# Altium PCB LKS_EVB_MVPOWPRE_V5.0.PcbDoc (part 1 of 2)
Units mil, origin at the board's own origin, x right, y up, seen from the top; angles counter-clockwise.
Board outline 11300 x 7874.02 mil, 2 copper layers (Top Layer, Bottom Layer); 150 components, 96 nets, 404 pads, 334 vias.
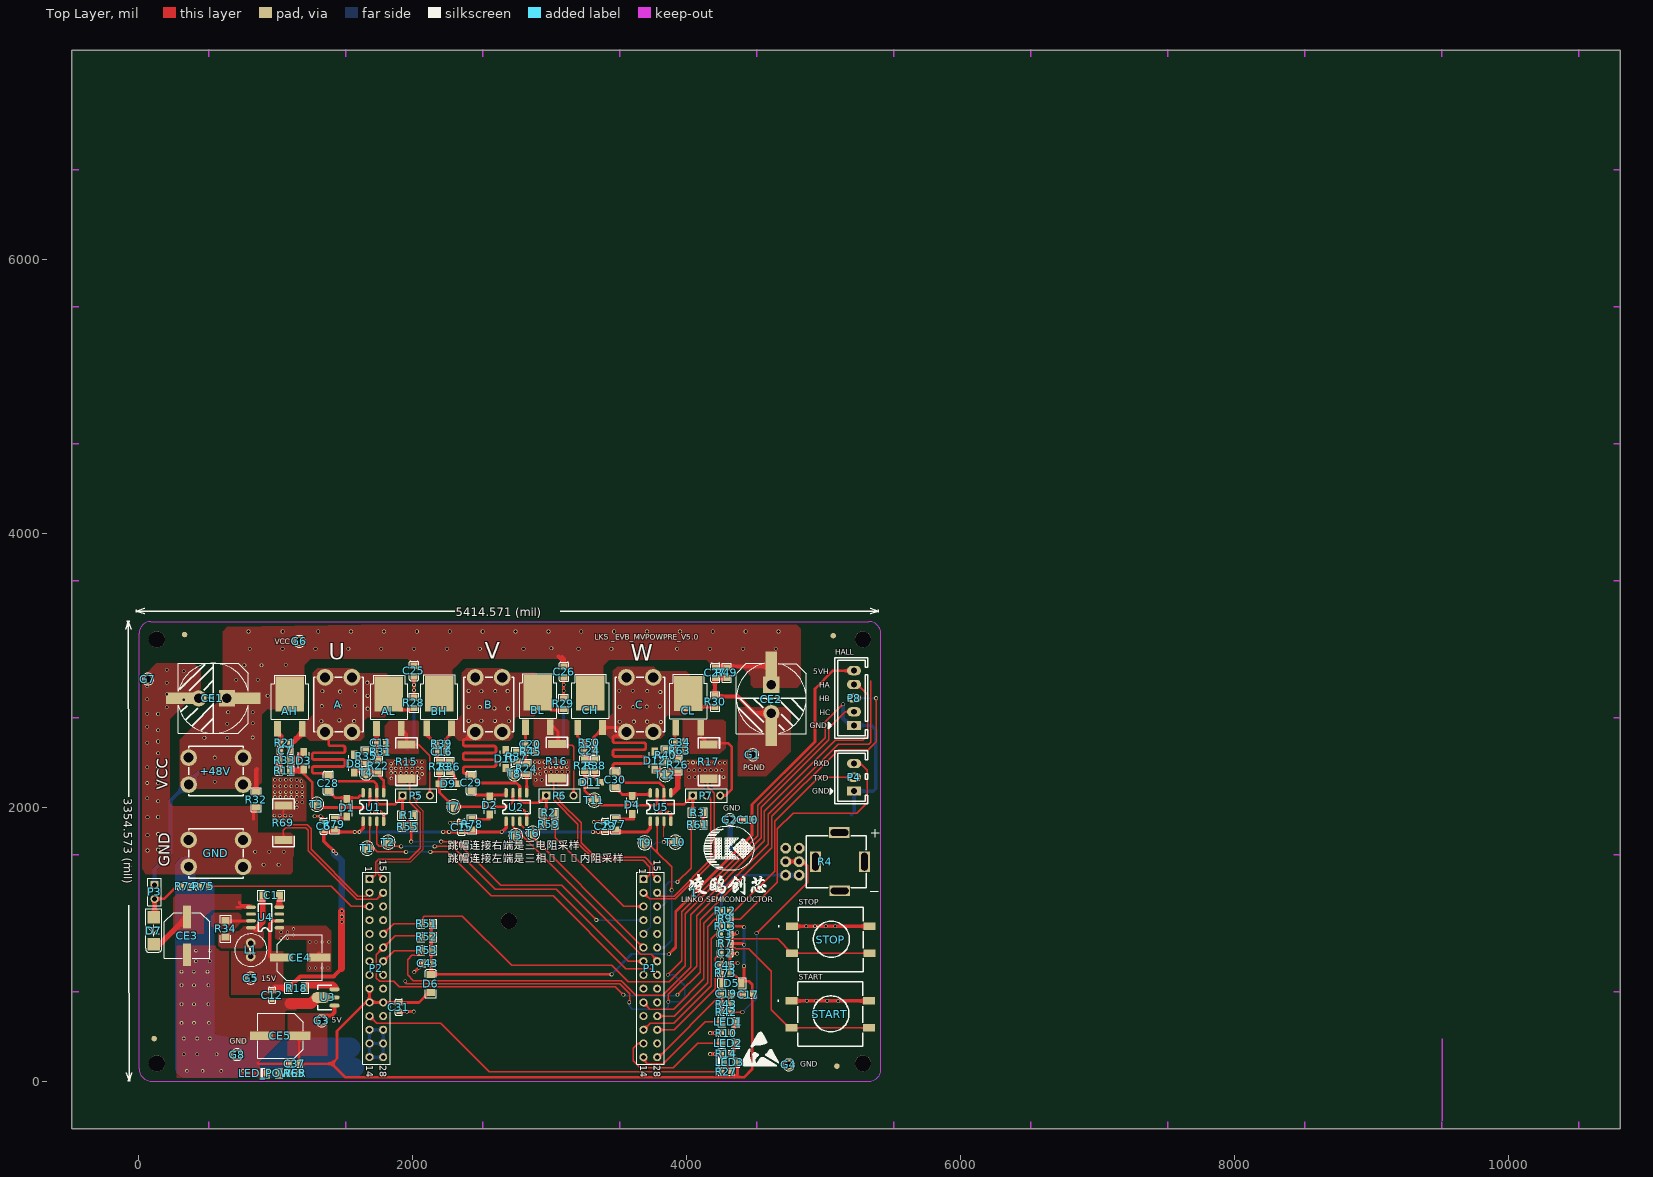
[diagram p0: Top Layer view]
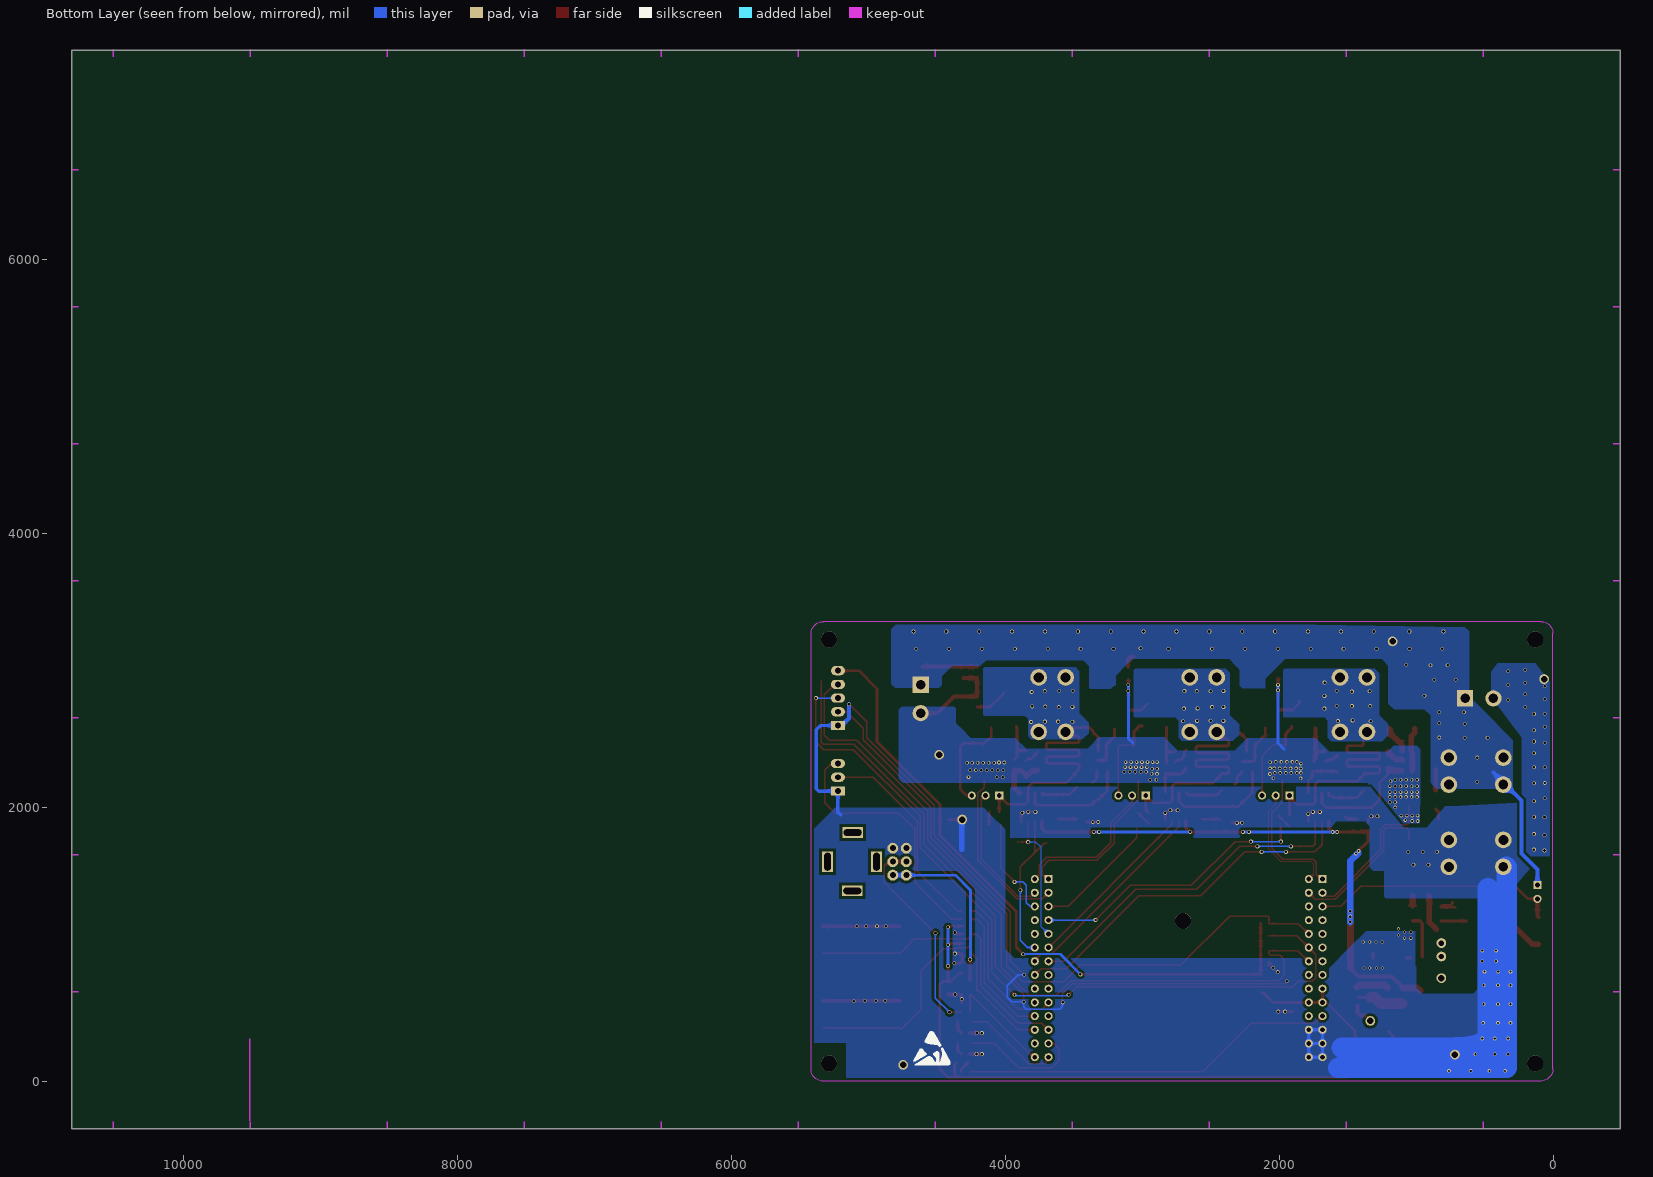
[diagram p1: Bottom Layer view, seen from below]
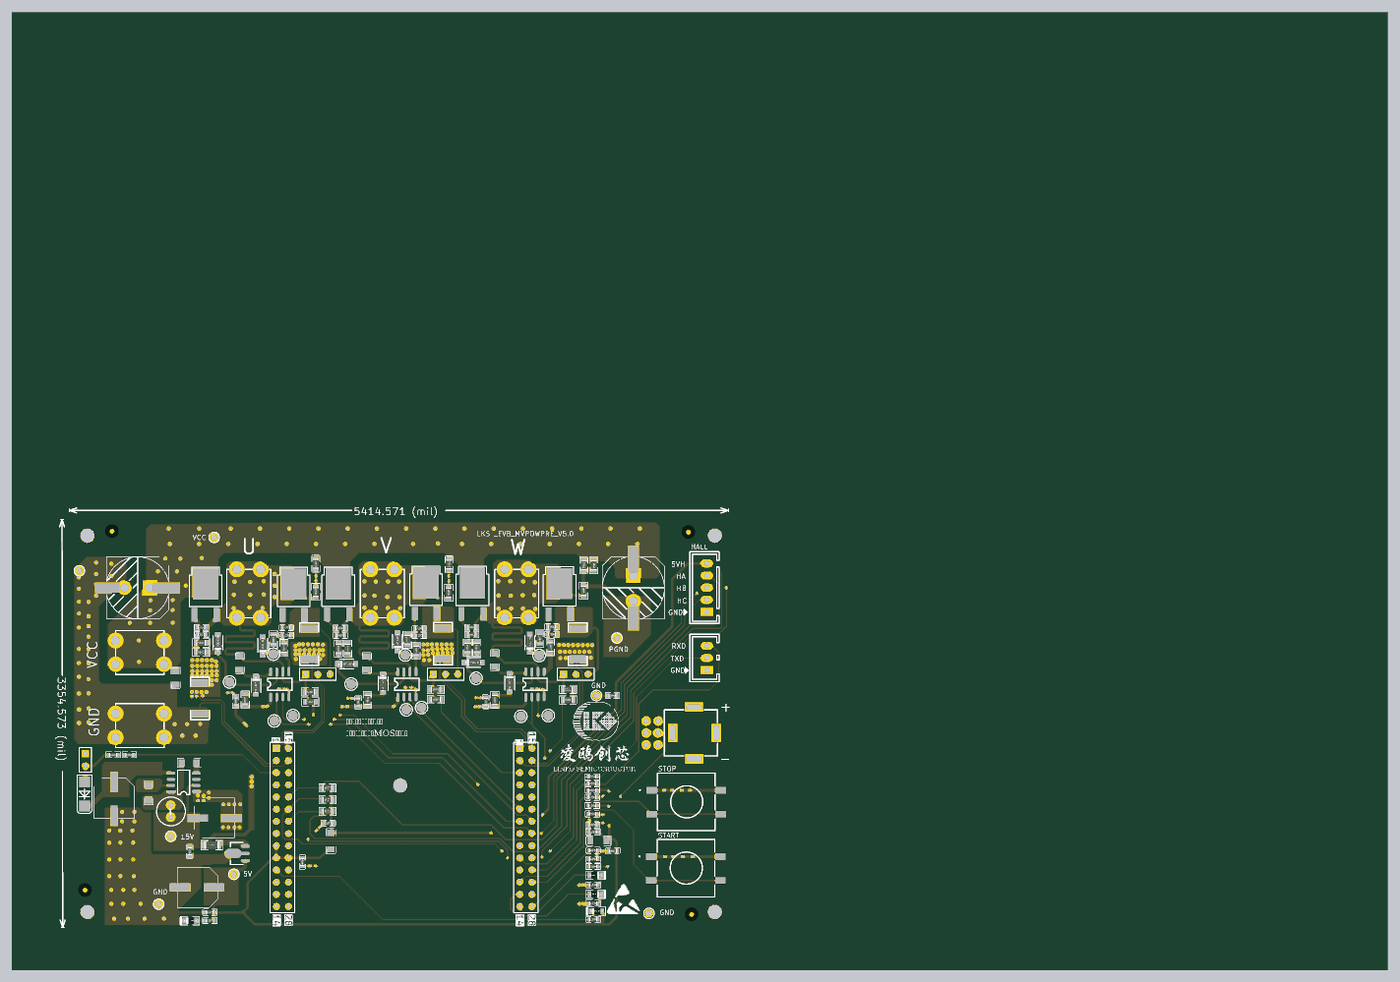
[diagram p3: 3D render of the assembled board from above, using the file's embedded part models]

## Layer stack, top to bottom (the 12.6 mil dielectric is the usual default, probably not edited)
Top Solder: solder mask 0.4, Solder Resist, Dk 3.5
Top Layer: signal copper 1.4
Dielectric1: dielectric 12.6, FR-4, Dk 4.8
Bottom Layer: signal copper 1.4
Bottom Solder: solder mask 0.4, Solder Resist, Dk 3.5

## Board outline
-489.2,7526.27 10810.8,7526.27 10810.8,-347.74 -489.2,-347.74

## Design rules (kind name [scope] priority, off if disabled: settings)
Clearance [InPolygon] p1: gap=20 ignorepadtopadclearanceinfootprint=FALSE except(0: Arc-Hole Track-Hole SMDPad-Hole THPad-Hole Via-Hole Fill-Hole Poly-Hole Region-Hole Text-Hole)
Clearance Clearance_48V [InNet('+48V')] p2: gap=30 ignorepadtopadclearanceinfootprint=FALSE except(0: Arc-Hole Track-Hole SMDPad-Hole THPad-Hole Via-Hole Fill-Hole Poly-Hole Region-Hole Text-Hole)
Clearance Clearance_4 [InNet('PGND')] p3 off: gap=20 ignorepadtopadclearanceinfootprint=FALSE except(0: Arc-Hole Track-Hole SMDPad-Hole THPad-Hole Via-Hole Fill-Hole Poly-Hole Region-Hole Text-Hole)
Clearance Clearance_5V [InNet('+5V')] p4 off: gap=20 ignorepadtopadclearanceinfootprint=FALSE except(0: Arc-Hole Track-Hole SMDPad-Hole THPad-Hole Via-Hole Fill-Hole Poly-Hole Region-Hole Text-Hole)
Clearance Clearance_15V [InNet('+15V')] p5: gap=20 ignorepadtopadclearanceinfootprint=FALSE except(0: Arc-Hole Track-Hole SMDPad-Hole THPad-Hole Via-Hole Fill-Hole Poly-Hole Region-Hole Text-Hole)
Clearance Clearance_5 [All] p6: gap=10 ignorepadtopadclearanceinfootprint=FALSE except(0: Arc-Hole Track-Hole SMDPad-Hole THPad-Hole Via-Hole Fill-Hole Poly-Hole Region-Hole Text-Hole)
ComponentClearance [All] p1 off: gap=0 collisioncheckmode=3 verticalgap=0 showdistances=FALSE
FabricationTestpoint [(IsPad And (OnTopLayer Or OnBottomLayer))] p1: side=3 testpointundercomponent=TRUE minsize=40 maxsize=100 preferedsize=60 minholesize=0 maxholesize=40 preferedholesize=32 testpointgrid=1 allowsidetop=TRUE allowsidebottom=TRUE usegrid=TRUE gridtolerance=0.01
HoleSize [All] p1: absolutevalues=TRUE maxlimit=200 minlimit=1 maxpercent=80.000 minpercent=20.000
PlaneConnect [All] p1: planeconnectstyle=Direct reliefexpansion=20 reliefentries=4 reliefconductorwidth=10 reliefairgap=10
PolygonConnect [All] p1: connectstyle=Direct reliefconductorwidth=30 reliefentries=4 polygonreliefangle="90 Angle" airgapwidth=10
RoutingVias [All] p1: holewidth=13.78 width=19.68 viastyle="Through Hole" minholewidth=0 minwidth=19.68 maxholewidth=19.68 maxwidth=39.37
SilkToSolderMaskClearance SilkscreenOverComponentPads [IsPad] p1: minsilkscreentomaskgap=10 clearancetoexposedcopper=TRUE
SolderMaskExpansion [All] p1: expansion=4 istentingtop=FALSE
Width Width_2 [All] p1 off: maxlimit=10 minlimit=10 preferedwidth=10
Width Width_1 [InNet('5V-T')] p2 off: maxlimit=40 minlimit=40 preferedwidth=40
Width Width_VH [InNet('5V1')] p3 off: maxlimit=40 minlimit=40 preferedwidth=40
Width Width_5V [InNet('5V')] p4 off: maxlimit=40 minlimit=40 preferedwidth=40
Width Width_14.3V [InNet('+14.3V')] p5 off: maxlimit=50 minlimit=50 preferedwidth=50
Width Width_15V [InNet('+15V')] p6 off: maxlimit=40 minlimit=40 preferedwidth=40
Width Width_48V [InNet('+48V')] p7 off: maxlimit=40 minlimit=40 preferedwidth=40
Width [All] p8: maxlimit=200 minlimit=1 preferedwidth=40
25 further rules are at their usual default settings.

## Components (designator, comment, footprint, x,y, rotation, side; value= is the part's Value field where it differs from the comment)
1 "LKS_sign" LKS_LOGO2 4052,1375 r0 top
+48V "M4" M4_CONECTOR 362.32,2361.91 r180 top locked
A "M4" M4_CONECTOR 1554.74,2947.17 r90 top
AH "NCE8259AK" TO-252 1100.83,2699.83 r0 top
AL "NCE8259AK" TO-252 1824.46,2700.27 r0 top
B "M4" M4_CONECTOR 2651.89,2947.17 r90 top
BH "NCE8259AK" TO-252 2190.43,2701.83 r0 top
BL "NCE8259AK" TO-252 2911.5,2709.11 r0 top
C "M4" M4_CONECTOR 3754.7,2947.17 r90 top
C1 "1uF/100V" 1206 1025,1355 r180 top value=10uF/100V
C2 "100nF/50V" 0603C 4279.38,935.8 r180 top
C3 "100nF/50V" 0603C 4279,1072.38 r0 top
C6 "100nF/50V" 0603C 1349.35,1861.85 r270 top
C7 "1nF/50V" 0603C 1067.35,2411.48 r0 top
C10 "100nF/10V" 0603C 4443.63,1909.64 r180 top
C11 "1nF/50V" 0603C 1765.67,2469.57 r0 top
C12 "100nF/50V" 0603C 971.91,628.23 r270 top
C15 "100nF/50V" 0603C 2354.32,1854.61 r270 top
C16 "1nF/50V" 0603C 2208.71,2404.53 r0 top
C17 "100nF/50V" 0603C 4447,632.28 r0 top
C19 "100nF/50V" 0603C 4286.37,636.63 r180 top
C20 "1nF/50V" 0603C 2856.37,2461.01 r0 top
C23 "100nF/50V" 0603C 3403.42,1859.96 r270 top
C24 "1nF/50V" 0603C 3287.96,2410.48 r0 top
C25 "100nF/100V" 0805C 2007.32,2994.16 r90 top
C26 "100nF/100V" 0805C 3102.45,2987.49 r90 top
C27 "100nF/100V" 0805C 4208.04,2981.02 r90 top
C28 "10uF/25V" 1206C 1382.65,2175.41 r90 top
C29 "10uF/25V" 1206C 2426.51,2177.17 r90 top
C30 "10uF/25V" 1206C 3477.64,2201.04 r90 top
C31 "100nF/50V" 0603C 1897.23,540.21 r90 top
C34 "1nF/50V" 0603C 3946.98,2474 r0 top
C37 "100nF/50V" 0603C 1136.55,127.54 r0 top
C43 "100nF/50V" 0603C 2109.05,860.11 r0 top value=104
C45 "100nF/50V" 0603C 4281.39,845.92 r180 top value=104
CE1 "220uF/63V" "220UF/63V 12.5*12.5" 643.54,2794.86 r270 top locked
CE2 "220uF/63V" "220UF/63V 12.5*12.5" 4615.51,2894.77 r0 top
CE3 "10UF/100V" "220UF/25V 8*10" 350.56,1061.42 r0 top
CE4 "220uF/25V" "220UF/25V 8*10" 1176,902 r90 top
CE5 "220uF/16V" "220UF/25V 8*10" 1030.55,331.65 r270 top
CH "NCE8259AK" TO-252 3293.7,2707.27 r0 top
CL "NCE8259AK" TO-252 4009.41,2704.65 r0 top
D1 "1N4007/SOD-123" SOD123 1515.74,1995.74 r90 top
D2 "1N4007/SOD-123" SOD123 2558.97,2012.54 r90 top
D3 "1N4007/SOD-123" SOD123 1201.59,2339 r270 top
D4 "1N4007/SOD-123" SOD123 3600.74,2015.98 r90 top
D5 "1N4007" D1206 4263.77,717.72 r0 top
D6 "1N4007" D1206 2131.36,777.78 r270 top
D7 "ES1J" DO-214AC 107.24,1099.38 r270 top
D8 "1N4007/SOD-123" SOD123 1571.43,2317.87 r270 top
D9 "1N4007/SOD-123" SOD123 2258.32,2169.59 r180 top
D10 "1N4007/SOD-123" SOD123 2677.05,2351.93 r270 top
D11 "1N4007/SOD-123" SOD123 3299,2182 r180 top
D12 "1N4007/SOD-123" SOD123 3764.75,2340 r270 top
G1 "PAD1.2" PAD1.2 4480.77,2382.24 r0 top
G2 "PAD1.2" PAD1.2 4312.32,1909.64 r0 top
G3 "PAD1.2" PAD1.2 1333.91,439.87 r0 top
G4 "PAD1.2" PAD1.2 4743.57,118.6 r0 top
G5 "PAD1.2" PAD1.2 815,752.2 r0 top
G6 "PAD1.2" PAD1.2 1171.19,3209.96 r0 top
G7 "PAD1.2" PAD1.2 64.78,2935.27 r0 top
G8 "PAD1.2" PAD1.2 715.92,194.2 r0 top
GND "M4" M4_CONECTOR 362.32,1761.11 r180 top locked
L1 "1mH  6*8" L_DIP_6*8MM 814.94,909.79 r90 top locked
LED1 "LED" SOD323 4300,434 r0 top
LED2 "LED" SOD323 4300,277.89 r0 top
LED3 "LED" SOD323 4314.88,134.7 r180 top
LED_POWER "LED_R" SOD323 978.76,56.48 r180 top
P1 "Header 14X2A" HDR2X14_CEN 3682.62,1475.19 r270 top locked
P2 "Header 14X2A" HDR2X14_CEN 1682.62,1475.19 r270 top locked
P3 "Header 2" HDR1X2 113.86,1430.98 r270 top
P4 "2.54-XH-3A-180" 2.54-XH-3A-180 5219.88,2118.44 r270 top
P5 "Header 3" HDR1X3 1924.05,2084.61 r0 top locked
P6 "Header 3" HDR1X3 2972.79,2084.61 r0 top locked
P7 "Header 3" HDR1X3 4042.39,2084.61 r0 top locked
P8 "Header 5" 2.54-XH-5A-180 5219.52,2796.37 r270 top
R1 "20K 1%" 0805R 1960.48,1940.22 r180 top
R2 "20K 1%" 0805R 2991.11,1958.2 r180 top
R3 "20K 1%" 0805R 4078.34,1960.07 r180 top
R4 "RPot" RK097-W-1 5014.05,1602.13 r270 top value=20K
R7 "10K" 0603R 4279,1005 r180 top
R9 "10R" 0603R 4279,1186.97 r0 top
R10 "5.1K" 0603R 4286.95,351.53 r180 top value=10K
R11 "51R" 0805R 1064,2266 r180 top value=K
R12 "10R" 0603R 4279.38,1242.38 r180 top value=100R
R13 "10K" 0603R 4279,1131.07 r0 top
R14 "5.1K" 0603R 4287,201.8 r180 top value=10K
R15 "0.005R/2512" 2512 1953.12,2455.91 r270 top
R16 "0.005R/2512" 2512 3050.13,2212.58 r90 top
R17 "0.005R/2512" 2512 4159.78,2455.91 r270 top
R18 "10R" 1206R 1151.55,679.32 r0 top value=K
R21 "20K1%" 0603R 1067.35,2469.91 r180 top value=K
R22 "51R" 0805R 1745.67,2301 r270 top value=K
R23 "51R" 0805R 2193.71,2295.93 r90 top value=K
R24 "51R" 0805R 2829.94,2280 r270 top value=K
R25 "51R" 0805R 3253,2304 r90 top value=K
R26 "51R" 0805R 3933,2308 r270 top value=K
R27 "5.1K" 0603R 4287,69 r180 top value=10K
R28 "51K" 0805R 2006.57,2761.64 r270 top value=K
R29 "51K" 0805R 3098.37,2754.95 r270 top value=K
R30 "51K" 0805R 4205.94,2771.18 r270 top value=K
R31 "20K1%" 0603R 1765.67,2405.05 r180 top value=K
R32 "47K" 1206R 856,2054.36 r270 top value=K
R33 "10R" 0805R 1064,2342.59 r180 top value=K
R34 "0.3R" 1206 633,1170 r270 top
R35 "10R" 0805R 1657.59,2370.5 r90 top value=K
R36 "10R" 0805R 2267.71,2295.93 r90 top value=K
R37 "10R" 0805R 2756.51,2368.93 r90 top value=K
R38 "10R" 0805R 3330,2304 r90 top value=K
R39 "20K1%" 0603R 2208.71,2463.73 r180 top value=K
R40 "10R" 0805R 3846.53,2378 r90 top value=K
R42 "10K" 0603R 4286.37,503.95 r180 top value=K
R43 "20K" 0603R 4286.12,563.36 r180 top value=K
R45 "20K1%" 0603R 2858,2403 r180 top value=K
R49 "51K" 0805R 4290.41,2981.02 r270 top value=K
R50 "20K1%" 0603R 3287.96,2471.3 r180 top value=K
R51 "2K" 0805R 2102.27,1149.28 r0 top
R52 "2K" 0805R 2102.27,1052.57 r0 top
R53 "2K" 0805R 2102.27,956.59 r0 top
R55 "20K 1%" 0805R 1961.36,1857.51 r180 top
R59 "20K 1%" 0805R 2992.19,1876.88 r180 top
R61 "20K 1%" 0805R 4079.41,1872.2 r0 top
R63 "20K1%" 0603R 3947,2413 r180 top value=K
R65 "5.1K" 0603R 1136.62,58.99 r180 top value=510R
R69 "0.005R/2512" 2512 1055.03,2009.54 r270 top
R73 "10K" 0603R 4283.13,788.55 r180 top
R74 "20K1%" 0603R 342.59,1422.22 r0 top
R75 "20K1%" 0603R 474.58,1422.18 r0 top
R77 "10R" 0805R 3477.54,1874.89 r90 top
R78 "10R" 0805R 2431.84,1874.57 r90 top
R79 "10R" 0805R 1427,1876.85 r90 top
START "SW-PB" "SW-PB  12*12" 5046.18,487.56 r0 top
STOP "SW-PB" "SW-PB  12*12" 5049.86,1032.41 r0 top
T1 "TestP" TP-80 1665.49,1700.56 r0 top
T2 "TestP" TP-80 1819.68,1744.81 r0 top
T3 "TestP" TP-80 1298.17,2021.23 r0 top
T4 "TestP" TP-80 1657.98,2249.61 r0 top
T5 "TestP" TP-80 2750,1792.49 r0 top
T6 "TestP" TP-80 2875.07,1810.16 r0 top
T7 "TestP" TP-80 2296.9,2003.78 r0 top
T8 "TestP" TP-80 2741.32,2242.5 r0 top
T9 "TestP" TP-80 3691.47,1738.81 r0 top
T10 "TestP" TP-80 3915.86,1745.2 r90 top
T11 "TestP" TP-80 3323.08,2051.79 r0 top
T12 "TestP" TP-80 3841.46,2238 r90 top
U1 "LKS560" SO-8 1638.08,1898.57 r90 top
U2 "LKS560" SO-8 2681.91,1898.57 r90 top
U3 "LM7805" SOT-89 1378.21,611 r90 top
U4 "LKS620" so-8 1024,1122 r180 top
U5 "LKS560" SO-8 3734.03,1898.57 r90 top

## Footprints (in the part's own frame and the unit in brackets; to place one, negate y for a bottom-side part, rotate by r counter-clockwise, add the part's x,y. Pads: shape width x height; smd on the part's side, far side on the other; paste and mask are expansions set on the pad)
2.54-XH-3A-180 [mm]
  rect 1.7x2.6 hole 1.1: 1(0,0)
  oval 1.7x2.6 hole 1.1: 2(-2.54,0) 3(-5.08,0)
  silkscreen extent -7.49,-4.5 2.41,2.54
2.54-XH-5A-180 [mm]
  rect 1.7x2.6 hole 1.1: 1(5.08,0)
  oval 1.7x2.6 hole 1.1: 2(2.54,0) 3(0,0) 4(-2.54,0) 5(-5.08,0)
  silkscreen extent -7.49,-4.78 7.49,2.54
"220UF/25V 8*10" [mm]
  rect 1.5x4.2 smd: 1(0,3.492) 2(0,-3.492)
  silkscreen extent -4.2,-4.13 4.2,4.27
"220UF/63V 12.5*12.5" [mm]
  rect 2.1x5.5 smd: 1(0,3.429)
  rect 3x3 hole 1.778: 1(0,-0.04)
  round 3 hole 1.778: 2(0,-5.3)
  rect 2.1x5 smd: 2(0,-8.867)
  silkscreen extent -6.5,-9.07 6.5,3.93
0603C [mm]
  rect 0.9x0.95 smd: 1(-0.813,0) 2(0.813,0)
  silkscreen extent -1.5,-0.66 1.5,0.66, body extent -0.8,-0.4 0.8,0.4, height 0.45
0603R [mil]
  rect 38x32 smd: 1(-32,0) 2(32,0)
  silkscreen extent -59,-24 59,24, body extent -31,-16 32,16, height 18
0805C [mil]
  rect 46x51.18 smd: 1(-38,0) 2(38,0)
  silkscreen extent -70,-33 70,33, body extent -40,-25 38,25, height 22
0805R [mil]
  rect 46x51.18 smd: 1(-38,0) 2(38,0)
  silkscreen extent -70,-34 70,34, body extent -39,-25 39,25, height 22
1206 [mm]
  rect 1.35x1.45 smd: 1(-0.01,-0.01) 2(2.99,-0.01)
  silkscreen extent -1.02,-1 4,0.98
1206C [mil]
  rect 50x60 smd: 1(-55,0) 2(55,0)
  silkscreen extent -86,-37 86,37
1206R [mil]
  rect 50x60 smd: 1(-55,0) 2(55,0)
  silkscreen extent -88,-39 88,39, body extent -62,-31 64,32, height 24
2512 [mm]
  rect 1.5x3.3 smd: 1(-0.04,-0.01) 2(6.31,-0.01)
  silkscreen extent -1.31,-1.98 7.56,1.96
D1206 [mm]
  rect 1.3x1.6 smd: 1(3.346,-0.04) 2(-0.054,-0.04)
  silkscreen extent -0.97,-1.06 4.26,0.98
DO-214AC [mm]
  rect 2.3x2.3 smd: 1(-2.502,0) 2(2.502,0)
  silkscreen extent -4,-1.51 4,1.52
HDR1X2 [mm] "Connector; Header; 2 Position"
  rect 1.5x1.5 hole 0.9: 1(0,0)
  round 1.5 hole 0.9: 2(2.54,0)
  silkscreen extent -1.27,-1.27 3.81,1.27
HDR1X3 [mm]
  rect 1.5x1.5 hole 0.9: 1(0,0)
  round 1.5 hole 0.9: 2(2.54,0) 3(5.08,0)
  silkscreen extent -1.27,-1.27 6.35,1.27
HDR2X14_CEN [mm] "Connector; Header; 14x2 Position"
  rect 1.5x1.5 hole 0.9: 1(0,0)
  round 1.5 hole 0.9: 2(2.54,0) 3(5.08,0) 4(7.62,0) 5(10.16,0) 6(12.7,0) 7(15.24,0) 8(17.78,0) 9(20.32,0) 10(22.86,0) 11(25.4,0) 12(27.94,0) 13(30.48,0) 14(33.02,0) 15(0,2.54) 16(2.54,2.54) 17(5.08,2.54) 18(7.62,2.54) 19(10.16,2.54) 20(12.7,2.54) 21(15.24,2.54) 22(17.78,2.54) 23(20.32,2.54) 24(22.86,2.54) 25(25.4,2.54) 26(27.94,2.54) 27(30.48,2.54) 28(33.02,2.54)
  silkscreen extent -1.27,-1.27 34.29,3.81
L_DIP_6*8MM [mm]
  round 1.8 hole 1: 1(0,0) 2(2.5,0)
  silkscreen extent -1.8,-3.04 4.2,2.95
LKS_LOGO2 [mil] "标?"
  silkscreen extent 70,167 440,482
M4_CONECTOR [mm] "接?"
  round 3.1 hole 1.9: 1(-10.1,0) 1(-10.1,5) 1(0,0)
  round 3.1 hole 1.8: 1(0,5)
  silkscreen extent -10.1,-2.1 0,7.1
PAD1.2 [mm]
  round 1.8 hole 1.2: 1(0,0)
  silkscreen extent -1.1,-1.1 1.1,1.1
RK097-W-1 [mm] "电?"
  rect 2x3.8 hole 1.2 slot 3.3 at 90 deg: 0(-5.4,2.503) 0(5.4,2.554)
  rect 3.8x2 hole 1.2 slot 3.3 at 0 deg: 0(0,7.15) 0(0,-1.93)
  round 2.032 hole 1.1: 1(2.5,-7.45) 2(-2.5,-7.45) 3(0,-7.45) 4(-2.5,-4.95) 5(0,-4.95) 6(2.5,-4.95)
  silkscreen extent -4.8,-3.65 4.8,7.45
SO-8 [mm]
  oval 1.8x0.61 smd: 1(-0.02,0.05) 2(-0.02,-1.22) 3(-0.02,-2.49) 4(-0.02,-3.76) 5(5.238,-3.76) 6(5.238,-2.49) 7(5.238,-1.22) 8(5.238,0.05)
  silkscreen extent 1.35,-4.4 3.89,0.68
so-8 [mm]
  oval 1.8x0.61 smd: 1(-0.02,0.05) 2(-0.02,-1.22) 3(-0.02,-2.49) 4(-0.02,-3.76) 5(5.238,-3.76) 6(5.238,-2.49) 7(5.238,-1.22) 8(5.238,0.05)
  silkscreen extent 1.35,-4.4 3.89,0.68
SOD123 [mm] "SOD-123; 2 Leads; Body 2.7 x 1.6 mm, (LxW)"
  rect 1.5x1.22 smd: 1(-1.65,0) 2(1.65,0)
  silkscreen extent -1.55,-1.03 1.38,1.02, body extent -1.93,-0.82 1.93,0.87, height 0.92
SOD323 [mil]
  rect 43.31x50 smd: 1(-40,-2) 2(45.63,-2)
  silkscreen extent -72,-37 87,33, body extent -48,-28 54,24, height 39
SOT-89 [mm]
  oval 0.7x1.9 smd: 1(-1.5,-1.25) 3(1.5,-1.25)
  oval 2x3.5 smd: 2(0,1.25)
  oval 0.7x2.1 smd: 2(0,-1.15)
  silkscreen extent -2.3,-0.75 2.3,1.85
"SW-PB  12*12" [mm] "按?"
  rect 2.2x1.397 smd: 1(-7.2,2.5) 2(-7.2,-2.5) 3(7.2,2.5) 4(7.2,-2.5)
  silkscreen extent -9.75,-5.94 6.02,6.06
TO-252 [mm]
  rect 1.25x2.85 smd: 1(-2.3,-3.2) 3(2.3,-3.2)
  rect 5.3x6.5 smd: 2(0,3.2)
  silkscreen extent -3.4,-1.5 3.4,6.71
TP-80 [mil]
  round 80 smd: 1(-0.39,0.39)
  silkscreen extent -51,-51 51,51

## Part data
+48V A B C GND: library part Socket, "Socket"
AH AL BH BL CH CL: library part MOS
C1 C43 C45: library part Cap, "Capacitor"
C2 C3 C7 C10 C11 C12 C16 C20 C24 C25 C26 C27 C34: library part CAP, "Capacitor"
C6 C15 C17 C19 C23 C31 C37: library part C, "Capacitor"
C28 C29 C30: library part Capacitor, "Capacitor --贴片电容"
CE1 CE2 CE3 CE4 CE5: library part "Capacitor Pol", "Capacitor---电解电容"
D1 D2 D3 D4 D7 D8 D9 D10 D11 D12: library part Diode, "Default Diode", PackageDocument=Sep-1996
D5 D6: library part "Diode 1N4007", "1 Amp General Purpose Rectifier"
G1 G2 G3 G4 G5 G6 G7 G8: library part CON1, "Connector"
L1: library part L
LED_POWER: library part LED
P1 P2: "Header, 14-Pin, Dual row"
P3: "Header, 2-Pin"
P4: library part "Header 3", "Header, 3-Pin"
P5 P6 P7: "Header, 3-Pin"
P8: "Header, 5-Pin"
R1 R2 R3 R51 R52 R53 R55 R59 R61: library part RES/1
R4: "Potentiometer"
R7 R9 R10 R12 R13 R14 R27 R34 R65 R73: library part Res2, "Resistor"
R11 R18 R21 R22 R23 R24 R25 R26 R31 R32 R33 R39 R42 R43 R45 R50 R63: library part Res, "Resistor"
R15 R16 R17 R69 R77 R78 R79: library part RES2短
R28 R29 R30 R35 R36 R37 R38 R40 R49: library part 1Res, "Resistor"
R74 R75: library part R
START STOP: "Switch"
U1 U2 U5: library part IRS2003S
U3: library part VOL-78

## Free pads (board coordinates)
  round 39.37 / inner round 0 / far side round 0 all layers, no hole: 1(111.08,310.73) 3(332.8,3260) 3(5067.77,3252.1) 4(5094.33,109.23)
  round 118.11 hole 118.11: 3(130,130) 3(130,3224.57) 3(2700,1170) 3(5284.57,130) 3(5284.57,3224.57)

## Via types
v1: diameter 26, hole 16, Top Layer to Bottom Layer, 130 vias
v2: diameter 28, hole 18, Top Layer to Bottom Layer, 77 vias
v3: diameter 26, hole 18, Top Layer to Bottom Layer, 55 vias
v4: diameter 28, hole 20, Top Layer to Bottom Layer, 54 vias
v5: diameter 23.62, hole 15.75, Top Layer to Bottom Layer, 14 vias
v6: diameter 27.99, hole 20, Top Layer to Bottom Layer, 4 vias

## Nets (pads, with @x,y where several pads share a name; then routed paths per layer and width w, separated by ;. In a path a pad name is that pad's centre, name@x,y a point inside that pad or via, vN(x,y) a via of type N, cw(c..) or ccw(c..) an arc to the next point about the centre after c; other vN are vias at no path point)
5V-T: C45.2 D5.2 R4.1 R4.6 R73.2 | length 1259.6
  Top Layer w20: 4255.12,805.62 4255.12,862.09 v4(4255.13,888.46) ; D5.2@4255.58,732.07 4255.58,805.16
  Bottom Layer w20: 4252.08,902.66 4252.08,1393.58 4362.21,1503.71 R4.6@4819.17,1503.71
5VH: C10.1 C43.2 D6.2 P8.5 R51.2 R52.2 R53.2 | length 4885
  Top Layer w20: D6.2@2129.79,779.9 v2@3449.45,779.9 ; R52.2@2132.91,1062.49 R52.2@2133.12,1062.49 ; D6.2@2133.12,783.23 R51.2@2133.12,1150.16 ; v2(3867.8,927.09) 3918.11,977.4 3918.11,1237.69 4475.51,1795.09 4475.51,2019.09 4934.05,2477.63 4934.05,2863.94 5066.48,2996.37 P8.5@5219.52,2996.37
  Bottom Layer w15: 3596.72,927.09 v2(3867.8,927.09)
  Bottom Layer w20: v2(3449.45,779.82) 3596.72,927.09
+5V: C17.2 C31.2 C37.2 CE5.1 D5.1 D6.1 G3.1 LED3.1 P2.9 P2.10 P2.24 R7.1 R13.2 R65.1 R73.1 U3.1 | length 6539.5
  Top Layer w20: C37.2@1168.55,127.54 C37.2@1168.55,127.54 ; R65.1@1168.62,58.99 C37.2@1168.55,127.54 ; 1199.3,362.9 CE5.1@1168.05,331.65 1168.62,331.08 C37.2@1168.55,127.54 ; P2.9@1682.62,675.19 P2.10@1682.62,575.19 ; D6.1@2129.79,646.05 2114.3,646.05 2043.45,575.19 P2.24@1782.62,575.19 P2.10@1682.62,575.19 ; R13.2@4308.38,1131.07 4407.81,1131.07 v3(4416.42,1122.46) ; R7.1@4311,1005 4406.49,1005 v3@4415.95,995.54 ; R73.1@4312.48,788.56 4332.94,788.56 D5.1@4405.44,716.06 ; LED3.1@4354.88,136.7 4369,122.58 4369,51.16 4345.84,28 ; D5.1@4402.56,729.63 4453.82,729.63 4476.45,707 4476.45,88.56 4415.89,28 4345.84,28 ; D5.1@4405.54,716.1 4415.89,726.44 v4(4415.89,841.54) ; C37.2@1168.55,127.54 1406.79,127.54 ; 1406.79,127.54 1445.55,166.3 1445.55,366.07 1654.67,575.19 P2.10@1682.62,575.19 ; 1406.79,127.54 1506.33,28 4345.84,28
  Top Layer w30: 1373.44,479.4 1406.79,479.4 1427.43,500.03 U3.1@1427.43,551.94
  Bottom Layer w20: v4@4415.95,841.61 v3@4415.95,995.54 ; v3(4416.41,996.39) v3(4416.42,1122.46)
+15V: C6.2 C12.1 C15.2 C23.2 CE4.1 G5.1 L1.1 R18.1 R77.1 R78.1 R79.1 U1.1 U2.1 U4.2 U5.1 | length 5239.7
  Top Layer w24: 954,909 954,1151 973.03,1170.03 U4.2@1024.79,1170.03 ; CE4.1@1038.5,902 CE4.1@1073.8,902 ; C6.2@1349.35,1829.85 1349.35,1751.73 v1@1438.52,1662.57 ; 1478.54,822.23 1480.06,823.76 v2(1480.06,1163.16) v2(1480.06,1201.16) v4(1480.06,1240.63)
  Top Layer w25: C6.2@1349.35,1819.04 v1(1574.74,1819.04) v1(1608.62,1819.04) 1636.11,1846.53 U1.1@1636.11,1897.79 ; v2(2220.32,1819.04) v2(2648.16,1819.04) 2679.94,1850.81 U2.1@2679.94,1901 ; v2@3314.81,1819.04 3704.88,1819.04 3732.06,1846.21 U5.1@3732.06,1894.22
  Top Layer w30: R18.1@1096.56,679.32 1096.56,684.32 1177.24,765 1421.31,765 1478.54,822.23
  Top Layer w50: C12.1@971.91,660.23 991,679.32 R18.1@1096.56,679.32 ; 1478.54,822.23 v4@1478.54,1241.5
  Bottom Layer w24: v2@1480.06,1162.5 v2(1480.06,1163.16)
  Bottom Layer w25: v1@1580,1819.04 v2(2263.12,1819.04) ; v2(2648.16,1819.04) v2@3352.21,1819.04
  Bottom Layer w50: 1421.57,1666.77 1480.06,1608.28 v4(1480.06,1240.63) v2(1480.06,1201.16) v2(1480.06,1163.16)
  other v1: 1438.66,1661.06 1418.83,1680.21
  other v2: 3313.38,1819.04 3352.14,1819.04
+48V: +48V.1 AH.2 BH.2 C25.2 C26.2 C27.2 CE1.1 CE2.1 CH.2 G6.1 P3.1 R32.1 R49.1 | length 1643.9
  Top Layer w30: R32.1@856,2121.86 856,2273.43 859.25,2276.68 ; 3061.95,3100.35 3102,3060.3 3102.45,3060.3 ; 3088.36,3095.81 3102.45,3081.71 3102.45,3060.3 ; C26.2@3102.45,3025.49 3102.45,3060.3 ; C27.2@4203.92,3028.04 CE2.1@4602.93,3028.04
  Bottom Layer w30: P3.1@113.86,1430.98 113.86,1544.69 230.14,1660.97 230.14,2047.73 435.6,2253.2
  other v3: 554.58,2187.07 553.03,2362.5 478.11,2507.09 645.5,2507.09 832,2508.69 645.5,2609.64 829.77,2612.24 650,2692.37 831.35,2694.28 938.25,2813.07 710,2930.83 865.63,2930.83 894.3,3035.2 770,3036.41 1070.11,3039.95
  other v4: 808.16,3156.11 1048.16,3156.11 1288.16,3156.11 1528.16,3156.11 1768.16,3156.11 2008.16,3156.11 2248.16,3156.11 2488.16,3156.11 2806.33,3156.11 3208.16,3156.11 3448.16,3156.11 3688.16,3156.11 3928.16,3156.11 4168.16,3156.11 4408.16,3156.11 4648.16,3156.11 3010,3160 799.19,3282.46 1048.6,3282.46 1308.42,3282.46 1548.42,3282.46 1788.42,3282.46 2028.42,3282.46 2268.42,3282.46 2508.42,3282.46 2748.42,3282.46 2988.42,3282.46 3228.42,3282.46 3468.42,3282.46 3708.42,3282.46 3948.42,3282.46 4188.42,3282.46 4428.42,3282.46 4668.42,3282.46
DM_IN: D7.1 P3.2 R74.1 | length 370.4
  Top Layer w20: P3.2@113.86,1330.98 183.12,1330.98 274.35,1422.22 R74.1@310.59,1422.22
  Top Layer w30: D7.1@107.24,1197.88 113.86,1204.5 P3.2@113.86,1330.98
GND: C2.1 C3.2 C6.1 C10.2 C12.2 C15.1 C17.1 C19.1 C23.1 C31.1 C37.1 C43.1 C45.1 CE1.2 CE3.2 CE4.2 CE5.2 G2.1 G4.1 G7.1 G8.1 GND.1 LED_POWER.2 P2.12 P2.13 P2.14 P2.16 P2.26 P2.27 P2.28 P4.1 P8.1 R4.2 R4.4 R10.2 R14.2 R32.2 R43.1 R69.2 START.1 START.3 STOP.1 STOP.3 U1.4 U2.4 U3.2 U4.1 U5.4 | length 19842.3
  Top Layer w10: R69.2@1054.64,1761.11 1054.64,1832.63 1072.52,1850.51 1217.31,1850.51 1235.76,1832.05 1235.76,1682.09 1589.52,1328.33 1735.76,1328.33 P2.16@1782.62,1375.19 ; v3(1942.74,729.66) 1942.74,718.48 1949.5,711.73 3509.69,711.73 3582.66,638.75 v3@3582.66,572.57 ; v3(3859.2,776.31) 3961.69,878.81 3961.69,1237.48 4516.95,1792.74 4516.95,2012.54 5010,2505.59 5010,2622.82 v4@5138.84,2751.66 ; v3(3864.62,580.26) 3864.62,632.74 4070,838.12 4070,1207 4593,1730 4593,1948 5106,2461 5327.99,2461 5340,2473.01 5340,2922.93
  Top Layer w20: 831.35,60 832.87,58.48 LED_POWER.2@933.13,58.48 ; 836.24,1911.43 836.24,1967.1 R32.2@856,1986.86 ; 868.05,131.93 872.44,127.54 C37.1@1104.55,127.54 ; v2(1282.09,1933.47) v2(1325.44,1933.47) 1348.2,1910.71 C6.1@1348.2,1887.66 ; U3.2@1329,611 U3.2@1423.49,611 ; v2(1702.01,1965.69) 1770.94,1965.69 v2(1786.11,1950.51) U1.4@1786.11,1897.79 ; C31.1@1897.23,508.21 v2(2006.22,508.21) ; v2(2269.68,1886.33) C15.1@2344.24,1886.33 ; v2(2740.57,1977.18) 2811.3,1977.18 v2(2829.94,1958.55) U2.4@2829.94,1901 ; v1(3319.66,1891.97) C23.1@3403.42,1891.96 ; v2(3778.72,1965.78) 3864.28,1965.78 3882.06,1948 U5.4@3882.06,1894.22 ; C3.2@4310.5,1072.38 4353.38,1072.38 v4(4367,1086) ; G2.1@4312.32,1909.64 4313.28,1908.68 C10.2@4410.13,1908.68 ; C45.1@4313.46,862.8 4313.46,931.1 v2(4365.78,931.1) ; C45.1@4314.18,862.09 v3(4369.37,862.09) ; R43.1@4315.92,570.97 v2(4315.92,599.71) C19.1@4315.92,634.86 ; C19.1@4316.99,632.28 v4(4363,632.28)
  Top Layer w25: v3@2008.61,795.29 C43.1@2074.06,860.75 ; START.1@4762.71,585.99 4899.12,585.99 START.3@5329.63,585.98 ; STOP.1@4766.4,1130.83 STOP.3@5333.33,1130.83
  Top Layer w30: CE4.2@1313.5,902 CE4.2@1313.5,931.5 ; v6(4169,197.25) R14.2@4254.95,197.25 ; v6(4169,350.7) 4169.83,351.53 R10.2@4254.95,351.53 ; v4(4363,632.28) C17.1@4415,632.28
  Top Layer w80: 1100.87,566.16 1255.89,566.16 1300.73,611 U3.2@1329,611
  Bottom Layer w10: v3@3579.29,574.15 3579.29,548.83 3601.63,526.49 3846.41,526.49 3864.28,544.36 v3@3864.28,579.61 ; v3@3858.69,776.44 3904.57,776.44 3983.76,697.25 3983.76,614.23 3949.9,580.37 v3@3864.7,580.37
  Bottom Layer w20: P2.13@1682.62,275.19 P2.27@1782.62,275.19 ; P2.14@1682.62,175.19 P2.12@1682.62,375.19 P2.26@1782.62,375.19 P2.28@1782.62,175.19 P2.14@1682.62,175.19
  Bottom Layer w25: 5200,1943.56 5219.88,1963.44 P4.1@5219.88,2117.85 ; P8.1@5219.52,2596.37 5345.51,2596.37 5377.09,2564.79 5377.09,2134.9 5360.04,2117.85 P4.1@5219.88,2117.85 ; P4.1@5219.8,2117.85 P4.1@5219.88,2117.85 ; P4.1@5219.88,2118.44 P4.1@5219.88,2117.85
  Bottom Layer w30: v4@5138.66,2751.66 5138.66,2648.37 P8.1@5189.08,2597.94
  Bottom Layer w40: 4314.35,1694.42 G2.1@4314.35,1911.41
  Bottom Layer w150: GND.1@342.32,1564.71 338.97,1561.36 338.97,98.21 1568,98.21 ; 350.99,244.93 541.21,244.93 ; 474.58,1406.44 474.58,311.55 541.21,244.93 ; 1541.62,244.93 541.21,244.93
  other v1: 350,75 463.89,75 600,75 759.23,75 327.22,197.25 425,197.25 566.95,197.25 327.22,311.55 425,311.55 516.21,311.55 310.59,425 401.59,425 510.8,425 310.59,561.37 401.59,561.37 506.58,561.37 310.59,700 401.59,700 506.61,700 310.59,800 400,800 499.94,800 415.58,875 515.91,875 415.58,953.1 516.21,953.1 3359.82,1891.52
  other v2: 1956,508.21 2307.03,1885.62 3873.41,1958.93 1753.14,1965.69 3830.06,1965.78 2792.48,1977.18
  other v3: 3580.11,574.51 5104.02,583.18 4874.72,585.84 4943.83,585.84 5023.04,585.84 2010.24,796.78 2040.6,828.33 4869.55,1129.94 4934.48,1129.94 5012.25,1129.95 5080.77,1129.94 847.07,1674.19 950,1674.19 1056.92,1675.59 139,2044.37 60.47,2063.82 60.47,2176.54 139,2290 60.47,2292.62 139,2393.16 60.47,2468.95 60.47,2586.13 60.47,2682.11 202.22,2730.11 327.22,2784.79 60.47,2788.14 202.22,2823.85 60.47,2881.88 327.22,2893.05 202.22,2908.67 327.22,2993.51 202.22,3002.41
  other v4: 910,1580 1019.38,1580 61.47,1683.32 140,1690 61.47,1795.07 140,1803.27 61.47,1926.24 140,1928.21 140,2175.26 140,2480 140,2561.24 140,2680 5138.76,2751.66
  other v5: 1289,826 1338.5,826 1380,826 1244,826.57 1247,1015 1292.15,1015 1338.5,1015 1386,1015 1038.5,1044 1084.98,1044 1128,1067.35 1038.5,1087.42 1084.98,1087.42 1128,1112
  other v6: 4208,198.8 4207,351.53
HALL_U: P2.8
HALL_V: P2.7
HALL_W: P2.6
HU: P2.21 P8.4 R53.1 | length 5575.8
  Top Layer w10: P2.21@1783.24,874.69 1862.37,953.81 2074.06,953.81 2074.06,930.07 2062.2,918.21 1991.29,918.21 1960.02,886.95 1960.02,775.5 2000.64,734.88 3518.8,734.88 3626.81,626.87 3821.87,626.87 4026,831 4026,1216 4564,1754 4564,1969 5084,2489 5283.57,2489 5319.52,2524.94 5319.52,2819.44 5242.59,2896.37 P8.4@5219.52,2896.37
HV: P2.20 P8.3 R52.1 | length 5877.7
  Top Layer w10: R52.1@2073.85,1062.49 1871.04,1062.49 1731.75,923.2 1731.75,752.2 1756.2,727.75 1860.89,727.75 1898.63,690 3477.13,690 v2@3536.47,630.67 ; v2(3930.79,630.67) 4095.34,795.22 4095.34,1178.11 4619.51,1702.28 4619.51,1932.51 5107,2420 5322.74,2420 5380,2477.26 v2(5380,2796.37)
  Bottom Layer w10: v2@3536.47,630.67 3542.13,625 3925.12,625 v2(3930.79,630.67) ; P8.3@5219.52,2796.37 v2(5380,2796.37)
  other v2: 3535.68,631.45
HW: P2.19 P8.2 R51.1 | length 4932.8
  Top Layer w10: P2.19@1783.24,1074.69 1859.19,1150.64 2073.59,1150.64 2073.59,1195.63 2083.15,1205.19 2359.39,1205.19 2719.28,845.3 3449.15,845.3 3569.6,724.85 3869.04,724.85 3987.33,843.14 3987.33,1222.33 4542.37,1777.37 4542.37,1997.86 5036.62,2492.12 5036.62,2576.1 5156.89,2696.37 P8.2@5219.52,2696.37
LED1: LED1.1 P1.14 | length 713.8
  Top Layer w10: P1.14@3682.62,175.19 3682.62,154.77 3710.41,126.97 3827.32,126.97 4133.48,433.13 4237.69,433.13
LED2: LED2.1 P1.13 | length 907.5
  Top Layer w10: P1.13@3682.62,275.19 3644.69,275.19 3609.14,239.64 3609.14,148.67 3660.52,97.29 3900.8,97.29 4080.15,276.64 LED2.1@4241.91,276.64
LED3: P2.11 R27.2 | length 2741.2
  Top Layer w10: P2.11@1683.02,475.8 1736.23,422.59 2201.17,422.59 2555.65,68.1 4254.1,68.1 R27.2@4255,69
NetAH_1: AH.1 C7.1 R11.2 R21.2 R33.2 | length 306.8
  Top Layer w20: R21.2@1034.67,2469.24 R21.2@1035.35,2469.91
  Top Layer w40: AH.1@1010.28,2573.85 1010.28,2542.35 1035.35,2517.29 C7.1@1035.35,2411.48 ; R11.2@1026,2266 R33.2@1026,2342.59 C7.1@1026,2399.11
NetAL_1: AL.1 C11.1 R22.1 R31.2 R35.2 | length 317.7
  Top Layer w20: R35.2@1657.98,2405.05 R31.2@1733.67,2405.05 ; R35.2@1672.96,2416.77 R35.2@1672.96,2418.63
  Top Layer w30: AL.1@1733.91,2574.29 1733.91,2469.57 1733.91,2405.05 1733.91,2350.77 R22.1@1745.67,2339
NetBH_1: BH.1 C16.1 R23.2 R36.2 R39.2 | length 351.8
  Top Layer w20: BH.1@2100.19,2578.95 2100.19,2527.52 R39.2@2177.12,2450.59 ; R23.2@2177.31,2336.15 R39.2@2177.31,2453.7 ; R23.2@2193.71,2333.93 R36.2@2267.71,2333.93
NetBL_1: BL.1 C20.1 R24.1 R37.2 R45.2 | length 336.3
  Top Layer w20: R37.2@2756.51,2406.93 2758.47,2404.97 R45.2@2820.94,2404.97 ; R24.1@2820.94,2318 R45.2@2820.94,2404.97 ; BL.1@2820.95,2583.13 2820.95,2515.64 2820.94,2471 R45.2@2820.94,2404.97 ; R45.2@2826,2403 2824.03,2404.97 R45.2@2820.94,2404.97
NetC1_1: C1.1 U4.4 | length 76.4
  Top Layer w40: U4.4@1025.39,1279 C1.1@1025.39,1355.39
NetC1_2: C1.2 L1.2 R34.2 U4.8 | length 269.3
  Top Layer w40: 852,1109 902,1159 902,1350.11 C1.2@907.28,1355.39
NetC24_1: C24.1 CH.1 R25.2 R38.2 R50.2 | length 323.8
  Top Layer w20: CH.1@3201.67,2568.27 3201.67,2517.09 3261.51,2457.25 3261.51,2338.97 3264.54,2342 R38.2@3330,2342
NetC28_1: C28.1 D1.2 U1.8 | length 301.9
  Top Layer w20: C28.1@1382.65,2120.41 1435.06,2068 1599.33,2068 1614.7,2083.37 1634.26,2083.37 1636.11,2085.22 U1.8@1636.11,2104.79
NetC29_1: C29.1 D2.2 U2.8 | length 282.6
  Top Layer w20: C29.1@2420.35,2124.39 2456.34,2088.4 2660.35,2088.4 U2.8@2679.94,2108
NetC30_1: C30.1 D4.2 U5.8 | length 287.4
  Top Layer w20: C30.1@3476.64,2144.31 3527.96,2093 3730.21,2093 3732.06,2094.85 U5.8@3732.06,2104.79
NetC34_1: C34.1 CL.1 R26.1 R40.2 R63.2 | length 324.5
  Top Layer w20: R40.2@3846.53,2416 3848.03,2414.5 R63.2@3911.89,2414.5 ; R63.2@3915,2413 3913.5,2414.5 R63.2@3911.89,2414.5 ; CL.1@3918.48,2589.33 3911.89,2582.74 3911.89,2478 R63.2@3911.89,2414.5 ; R26.1@3933,2346 3911.89,2367.11 R63.2@3911.89,2414.5
NetCE3_1: CE3.1 D7.2 U4.5 | length 530.5
  Top Layer w20: 715.95,1270.03 U4.5@817.79,1270.03 805.82,1282 750.03,1282 734,1298.03 734,1306
  Top Layer w40: D7.2@107.24,1000.88 152.52,1000.88 CE3.1@350.56,1198.92
NetD1_1: D1.1 R79.2 | length 96.5
  Top Layer w20: R79.2@1427,1914.85 1501.72,1914.85 1515.74,1928.87 D1.1@1515.74,1930.78
NetD2_1: D2.1 R78.2 | length 130.2
  Top Layer w20: R78.2@2431.04,1912.51 2561.27,1912.51
NetD3_1: D3.1 R33.1 | length 162.7
  Top Layer w20: R33.1@1105.35,2340.09 R33.1@1110.71,2345.46 ; D3.1@1189.39,2392.94 1203.41,2406.95 D3.1@1203.41,2412.46
  Top Layer w40: R33.1@1102,2342.59 1102,2345.18 1105,2348.18 1151.33,2348.18 1201.59,2398.45 D3.1@1201.59,2403.96
NetD4_1: D4.1 R77.2 | length 135.2
  Top Layer w20: R77.2@3477.26,1913.68 3612.44,1913.68
NetD8_1: D8.1 R35.1 | length 110.2
  Top Layer w20: D8.1@1571.43,2382.83 1571.43,2377.32 1585.44,2363.3 1590.95,2363.3 1608.75,2345.5 1644.59,2345.5 R35.1@1657.59,2332.5
NetD9_1: D9.1 R36.1 | length 115.6
  Top Layer w20: R36.1@2267.71,2257.93 2270.3,2257.93 2304.63,2223.61 2304.63,2183.61 2318.65,2169.59 D9.1@2323.28,2169.59
NetD10_1: D10.1 R37.1 | length 134.3
  Top Layer w20: D10.1@2677.05,2416.89 2691.06,2402.88 2691.06,2370.01 2717.14,2343.93 2743.51,2343.93 R37.1@2756.51,2330.93
NetD11_1: D11.1 R38.1 | length 101.3
  Top Layer w20: R38.1@3330,2266 3330,2210.45 3358.45,2182 D11.1@3363.96,2182
NetD12_1: D12.1 R40.1 | length 111.9
  Top Layer w20: D12.1@3764.75,2404.96 3764.75,2399.45 3811.2,2353 3833.53,2353 R40.1@3846.53,2340
NetLED1_2: LED1.2 R10.1 | length 91.5
  Top Layer w20: R10.1@4318.95,351.53 4345.63,378.21 LED1.2@4345.63,432
NetLED2_2: LED2.2 R14.1 | length 89.7
  Top Layer w20: R14.1@4318.95,197.25 4345.63,223.93 LED2.2@4345.63,275.89
NetLED3_2: LED3.2 R27.1 | length 88.3
  Top Layer w20: LED3.2@4269.25,136.7 4319,86.95 R27.1@4319,69
NetLED_POWER_1: LED_POWER.1 R65.2 | length 86.1
  Top Layer w20: LED_POWER.1@1018.76,58.48 1104.11,58.48 R65.2@1104.62,58.99
NetP4_2: P4.2 R12.1 | length 1526.5
  Top Layer w10: R12.1@4311.38,1242.38 4348.67,1242.38 4640,1533.71 4640,1897.48 4960.36,2217.85 P4.2@5220.74,2217.85
NetP4_3: P4.3 R9.2 | length 1940.4
  Top Layer w10: R9.2@4312.09,1180.48 4390.46,1180.48 4660.51,1450.53 4660.51,1841.55 4775.31,1956.34 5240.98,1956.34 5317.03,2032.39 5317.03,2268.17 5267.35,2317.85 P4.3@5219.8,2317.85
NetR1_1: R1.1 R55.2 | length 113.8
  Top Layer w15: R55.2@1923.36,1857.51 R1.1@1998.48,1932.63
  Top Layer w20: R1.1@1998.48,1932.63 R1.1@1998.48,1940.22
NetR2_1: R2.1 R59.2 | length 116.5
  Top Layer w15: R59.2@2946.76,1875.86 R2.1@3029.1,1958.2
NetR3_1: R3.1 R61.2 | length 90.9
  Top Layer w20: R61.2@4117,1874.6 R3.1@4117,1965.48
NetR18_2: R18.2 U3.3 | length 242
  Top Layer w50: R18.2@1206.56,679.32 1206.56,684.32 1211.56,684.32 1228.79,701.55 1414.45,701.55 1430,686
NetR34_1: R34.1 U4.7 | length 184.8
  Top Layer w20: R34.1@632.97,1170.03 U4.7@817.79,1170.03
NetR74_2: R74.2 R75.1 | length 68.7
  Top Layer w10: R74.2@376.29,1421.96 R75.1@445,1421.96
NRST: P2.23
OC: P2.4
P0.0: P2.22
P0.4: P1.27
P0.14: P1.11
P1.3: P1.24
P1.10: P1.19
P1.11: P1.18
P2.1: P2.18
P2.2: P2.5
P2.7: P1.9
P2.10: P2.17
P3.2: P2.25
